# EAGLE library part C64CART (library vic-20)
Commodore 64/128 cartridge port
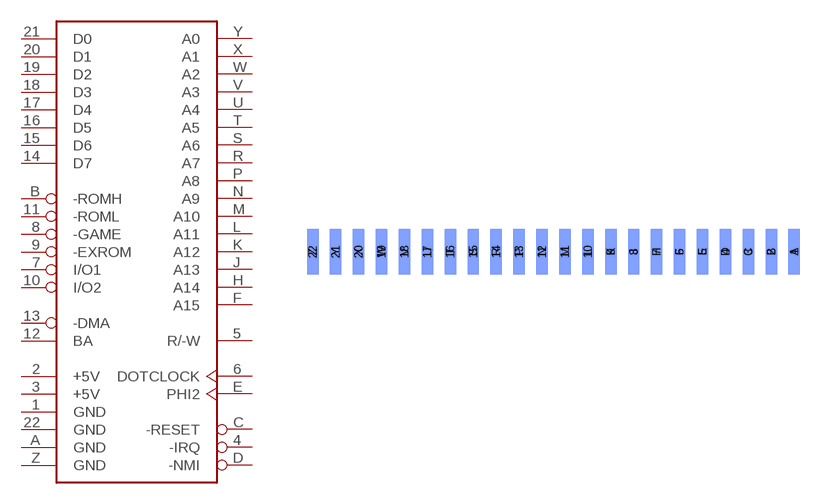
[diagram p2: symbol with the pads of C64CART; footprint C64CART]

Designator prefix -

## C64CARTEDGE  [C64CART]
1  GND  sup
2  +5V  sup
3  +5V  sup
4  -IRQ
5  R/-W  out
6  DOTCLOCK  out
7  I/O1  out
8  -GAME  out
9  -EXROM  out
10  I/O2  out
11  -ROML  out
12  BA  out
13  -DMA
14  D7
15  D6
16  D5
17  D4
18  D3
19  D2
20  D1
21  D0
22  GND  sup
A  GND  sup
B  -ROMH  out
C  -RESET
D  -NMI
E  PHI2  out
F  A15  out
H  A14  out
J  A13  out
K  A12  out
L  A11  out
M  A10  out
N  A9  out
P  A8  out
R  A7  out
S  A6  out
T  A5  out
U  A4  out
V  A3  out
W  A2  out
X  A1  out
Y  A0  out
Z  GND  sup

## Footprint C64CART (pad centres in mm)
Commodore 64/128 cartridge connector (card edge)
smd 1.27 x 5.08: 1 26.67,0; 2 24.13,0; 3 21.59,0; 4 19.05,0; 5 16.51,0; 6 13.97,0; 7 11.43,0; 8 8.89,0; 9 6.35,0; 10 3.81,0; 11 1.27,0; 12 -1.27,0; 13 -3.81,0; 14 -6.35,0; 15 -8.89,0; 16 -11.43,0; 17 -13.97,0; 18 -16.51,0; 19 -19.05,0; 20 -21.59,0; 21 -24.13,0; 22 -26.67,0
smd 1.27 x 5.08 bottom: A 26.67,0; B 24.13,0; C 21.59,0; D 19.05,0; E 16.51,0; F 13.97,0; H 11.43,0; J 8.89,0; K 6.35,0; L 3.81,0; M 1.27,0; N -1.27,0; P -3.81,0; R -6.35,0; S -8.89,0; T -11.43,0; U -13.97,0; V -16.51,0; W -19.05,0; X -21.59,0; Y -24.13,0; Z -26.67,0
